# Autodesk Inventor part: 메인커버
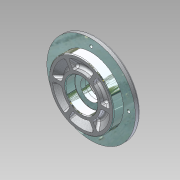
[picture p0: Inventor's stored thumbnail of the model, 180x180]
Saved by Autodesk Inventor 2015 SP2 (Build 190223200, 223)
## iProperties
Manager: KYOUNG IL JANG
Company: 한국ATC센터
Created: 2012-10
Part Number: 메인커버
Document SubType Name: Modeling
Density: 1 g/cm^3
Checked By: KYOUNG IL JANG
Vendor: CBT Solutions
Designer: KYOUNG IL JANG
Material: 일반
Appearance: _시험_알루미늄 표면거칠기
Author: KYOUNG IL JANG
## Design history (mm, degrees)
sketch "스케치1"
  geometry: L1 (0, 0)-(0, 28.5); L2 (0, 0)-(28.5, 0); L3 (28.5, 0)-(28.5, 4.726); L4 (28.5, 8)-(31.774, 8); L5 (32.966, 8)-(33.879, 7.234); L6 (42.5, 0)-(47.5, 0); L7 (47.5, 0)-(47.5, 14.5); L8 (47.5, 14.5)-(65, 14.5); L9 (65, 14.5)-(65, 22.5); L10 (65, 22.5)-(33.464, 22.5); L11 (33.464, 22.5)-(30, 28.5); L12 (30, 28.5)-(0, 28.5); L13 (28.5, 4.726)-(28.5, 8); L14 (31.774, 8)-(32.966, 8); L15 (33.879, 7.234)-(42.5, 0); L16 (23.5, 0)-(23.5, 14); L17 (23.5, 14)-(15, 14); L18 (15, 14)-(15, 20.5); L19 (15, 20.5)-(17.5, 20.5); L20 (17.5, 20.5)-(17.5, 28.5); A1 r 3.274 centre (31.774, 4.726) between (33.879, 7.234) and (28.5, 4.726)
  constraints: 40 end point, 11 parallel, 6 perpendicular, 6 tangent, 3 point on circle, 2 collinear, 2 point on line, 1 centre point, 1 vertical
  dimensions: "d1" = 130 diameter of L9 L1; "d2" = 95 diameter of L7 L1; "d3" = 57 diameter of L3 L1; "d4" = 5 distance of L6.start L6.end; "d5" = 14.5 distance between parallel lines of L8 L6; "d6" = 8 distance of L8.end L9.end; "d7" = 6 distance between parallel lines of L10 L12; "d8" = 8 distance of L2.end L4.start; "d9" = 140 deg angle of L6 L5; "d10" = 47 diameter of L16 L1; "d11" = 14 distance of L16.start L16.end; "d12" = 35 diameter of L20 L1; "d13" = 8 distance of L19.end L20.end; "d14" = 30 diameter of L18 L1; "d15" = 120 deg angle of L10 L11; "d16" = 60 diameter of L11.end L1
revolve "회전1" sketch "스케치1" stored, may be unused: angle "d17" = 90 deg
sketch "스케치2"
  geometry: L1 (28.5, 0)-(42.5, 0); 3 further points
  constraints: 2 end point, 2 horizontal alignment, 1 horizontal, 1 point on line, 2 other
feature "리브1" sketch "스케치2" dims "d18" = 5, "d19" = 1, "d20" = 0
fillet "모깎기1" dims "d21" = 3
fillet "모깎기2" dims "d25" = 3, "d26" = 0.3
chamfer "모따기1" distance "d27" = 1; stored, may be unused: second distance "d28" = 2, angle "d29" = 45 deg
sketch "스케치3"
  geometry: C1 r 2.067 at (55, 0) reference; C2 r 2.067 at (0, -55) reference; C3 r 2.067 at (-55, 0) reference; C4 r 2.067 at (0, 55) reference; 1 further point
hole "구멍1" sketch "스케치3" at (0, 55), (-55, 0), (0, -55), (55, 0) diameter "d30" = 4.5; stored, may be unused: countersink angle "d34" = 90 deg, drill point angle "d36" = 118 deg; dims "d31" = 6, "d32" = 8, "d33" = 4.4, "d35" = 8
node "솔리드1"
pattern_circular "원형 패턴1" dims angle "d23" = 360 deg
node "참조1"
node "참조2"
node "참조3"
node "참조4"
